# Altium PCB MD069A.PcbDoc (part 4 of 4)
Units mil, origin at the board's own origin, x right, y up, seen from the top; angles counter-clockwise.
Board outline 4569 x 3239 mil, 4 copper layers (Top Layer, Signal Layer 1, Signal Layer 2, Bottom Layer), stack 61.2 mil thick; 187 components, 103 nets, 560 pads, 220 vias.
Unrouted connection lines stored in the file: 7.
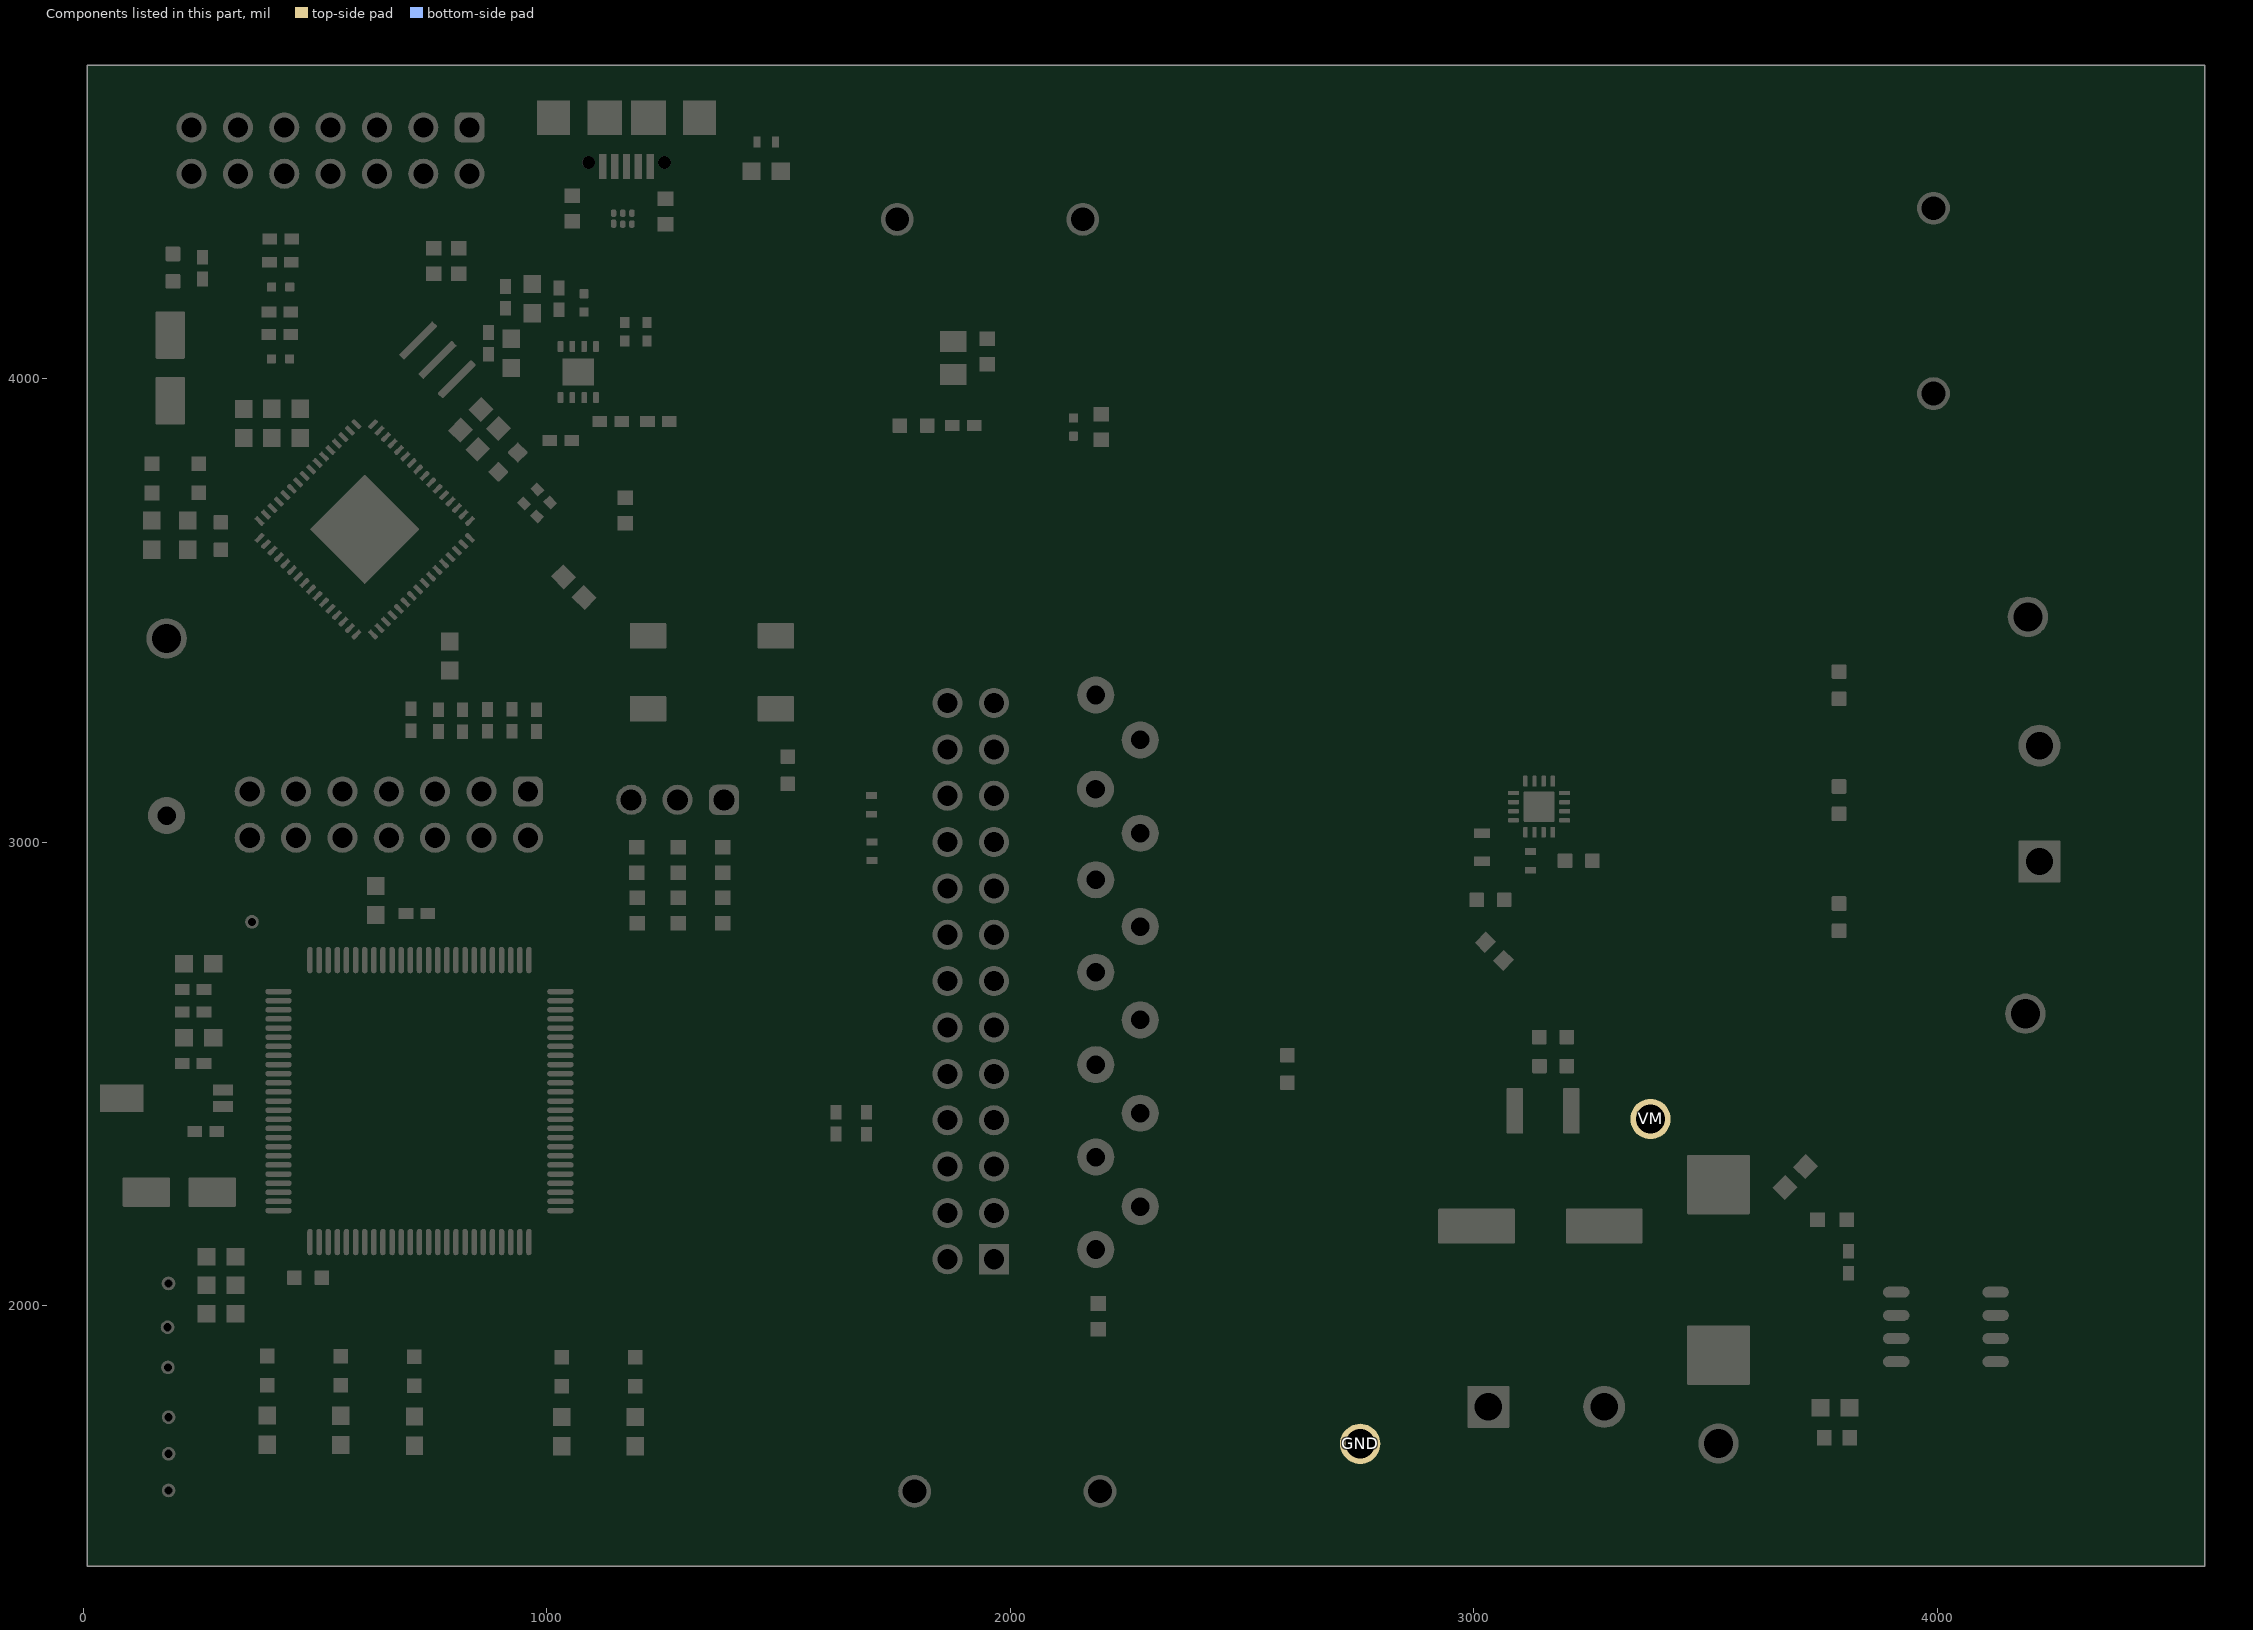
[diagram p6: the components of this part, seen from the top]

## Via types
v1: diameter 19.68, hole 13.78, Top Layer to Bottom Layer, tented both sides, 133 vias
v2: diameter 34, hole 16, Top Layer to Bottom Layer, tented both sides, 47 vias
v3: diameter 25/25/25/25 (per signal layer), hole 12, Top Layer to Bottom Layer, 19 vias
v4: diameter 19.68, hole 7.87, Top Layer to Bottom Layer, 16 vias
v5: diameter 19.68, hole 7.87, Top Layer to Bottom Layer, tented both sides, 5 vias

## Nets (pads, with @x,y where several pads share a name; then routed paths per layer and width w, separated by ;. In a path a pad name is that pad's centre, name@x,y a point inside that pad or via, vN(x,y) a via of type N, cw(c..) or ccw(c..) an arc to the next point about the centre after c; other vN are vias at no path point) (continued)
pads on no net: H2.0 H3.0 H4.0 H5.0 J9.6 J9.10 J9.12 J9.13 J9.14 J10.11 J10.12 J11.4 J11.MH1 J11.MH2 LBL1.0 P1.20 P1.22 SH-J1.0 SH-J2.0 SH-J3.0 SH-J4.0 SH-J5.0 SH-J6.0 SH-J7.0 SH-J8.0 SH-J9.0 SH-J10.0 SH-J11.0 SH-J12.0 SH-J19.0 SH-J29.0 SH-J31.0 SH-J32.0 SH-J33.0 SH-J34.0 SH-J36.0 U1.1 U1.2 U1.5 U1.6 U1.7 U1.8 U1.19 U1.24 U1.28 U1.30 U1.34 U1.35 U1.37 U1.38 U1.39 U1.40 U1.41 U1.46 U1.47 U1.48 U1.50 U1.52 U1.54 U1.55 U1.56 U1.57 U1.58 U1.59 U1.62 U1.67 U1.68 U1.69 U1.70 U1.71 U1.72 U1.73 U1.74 U1.75 U1.77 U1.78 U1.79 U1.80 U1.81 U1.82 U1.84 U1.85 U1.86 U1.92 U1.93 U1.94 U1.95 U1.99 U1.100 U2.3 U2.4 U2.5 U2.6 U2.7 U2.8 U2.10 U2.12 U2.13 U2.18 U2.19 U2.22 U2.23 U2.24 U2.25 U2.26 U2.27 U2.28 U2.29 U2.30 U2.31 U2.32 U2.33 U2.34 U2.35 U2.36 U2.41 U2.42 U2.45 U2.46 U2.47 U2.48 U3.2 U3.6 U3.7

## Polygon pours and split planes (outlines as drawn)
NetF1_1 on Signal Layer 2 "SIGNAL_LAYER_2_NETF1_1_P136" (solid, remove dead copper, pour order 136): 3186.98,1985.2 3177.14,1975.36 3177.14,1659.09 3704.72,1659.09 3704.72,1985.2
GND on Signal Layer 2 "SIGNAL_LAYER_2_GND_P275" (solid, pour order 275): 8,1438 4577,1438 4577,4677 8,4677
EZFET_VBUS on Signal Layer 2 "SIGNAL_LAYER_2_EZFET_VBUS_P199" (solid, remove dead copper, pour order 199): 881.67,4674.65 1506.38,4674.65 1506.38,4130.6 883.05,4130.6
GND on Bottom Layer "BOTTOM_LAYER_GND_P273" (solid, remove dead copper, pour order 273): 4577,4677 22.6,4677 22.6,1454.09 4577,1454.09
VM on Top Layer "Top Layer-VM" (solid, remove dead copper, pour order 284): 3182.2,1989.21 3596.49,1989.21 3733.74,1938.49 3733.74,2209.03 3289.22,2598.66 3289.21,2598.66 3214.52,2673.35 3214.52,3052.25 3182.23,3052.25 3182.23,2598.66 3182.2,2598.66
OUT2 on Top Layer "Top Layer-OUT2" (solid, remove dead copper, pour order 281): 3242.99,3101.78 4297.2,3101.78 4297.2,3333.76 4297.19,3534.66 4041.49,3534.66 4041.49,3333.76 3462.57,3333.76 3242.99,3114.18
OUT1 on Top Layer "Top Layer-OUT1" (solid, remove dead copper, pour order 276): 4041.71,2563.09 4297.47,2563.09 4297.47,3014.66 4297.07,3014.66 4297.07,3073.4 3242.86,3073.4 3242.86,3061.01 3462.44,2841.43 4041.71,2841.43
NetF1_1 on Top Layer "TOP_LAYER_NETF1_1_P201" (solid, remove dead copper, pour order 201): 3186.98,1985.2 3177.14,1975.36 3177.14,1659.09 3674.78,1659.09 3674.78,1985.2
GND on Top Layer "TOP_LAYER_GND_P283" (solid, remove dead copper, pour order 283): 5.69,1438.73 4574.69,1438.73 4574.69,4694.9 5.69,4694.9
GND on Signal Layer 1 "SIGNAL_LAYER_1_GND_P184" (solid, pour order 184): 15.78,4675 4577,4675 4577,1438 8,1438

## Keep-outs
Keep-Out Layer:
  text ".Layer_Name" at 577,-858.49 h25

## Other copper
Top Layer:
  region net EZFET_USB_Shield: 960,4649.2 960,4645.75 960,4426 1062.33,4426 1062.33,4485.1 1091.51,4508 1123.89,4508 1255.92,4508 1287.78,4476.14 1287.78,4431.31 1296.51,4431.31 1296.51,4432.8 1393.6,4432.8 1392,4648.75 1384.61,4648.75
  text ".Layer_Name" at 577,-858.49 h25
Bottom Layer:
  region net EZFET_USB_Shield: 1391,4428.4 1392,4427.4 1289,4427.4 1289,4500.38 1287.38,4502 1062.47,4502 1062.47,4429.47 1060,4427 1059.6,4427.4 952.18,4427.4 952.18,4502 951,4502 951,4649.88 951.31,4649 952.18,4649.88 1391,4649.88
  text ".Layer_Name" at 577,-858.49 h25

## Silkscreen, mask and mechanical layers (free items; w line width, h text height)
Top Overlay:
  lines w6: 755.3,3883.12 854.73,3783.69 959.5,3888.46 ; 755.3,3890.46 854.73,3989.89 ; 782.9,4491.95 782.9,4583.38 ; 783.57,4491.95 879.06,4491.78 ; 860.07,3989.89 959.5,3890.46 ; 910.63,3060.79 910.63,3152.21 ; 911.3,3060.79 1006.79,3060.61 ; 940.77,3869.73 1008.46,3802.04 1252.04,3802.04 ; 1225.34,3773.34 1298.75,3699.94 ; 1227.35,3773.34 1288.74,3834.74 ; 1289.41,3834.74 1362.15,3762 ; 1298.75,3697.94 1362.15,3761.33 ; 186.97,4397.12 879.06,4397.12 879.06,4586.43 186.97,4586.43 186.97,4397.12 ; 314.7,2965.96 1006.79,2965.96 1006.79,3155.27 314.7,3155.27 314.7,2965.96
  lines w10: 755.3,3883.12 755.3,3890.46 ; 854.73,3989.89 860.07,3989.89 ; 898.45,4506.4 898.45,4579.92 ; 959.5,3888.46 959.5,3890.46 ; 1022.26,3074.12 1022.26,3147.64 ; 1225.34,3773.34 1227.35,3773.34 ; 1288.74,3834.74 1289.41,3834.74 ; 1298.75,3697.94 1298.75,3699.94 ; 1362.15,3761.33 1362.15,3762 ; 2027.5,2701.11 2119.32,2701.11 ; 2027.5,3099.99 2114.65,3099.99 ; 2029.84,2501.67 2116.98,2501.67 ; 2029.84,2799.95 2208.81,2799.95 ; 2030.42,2099.28 2122.25,2099.28 ; 2031.01,2997.64 2205.88,2997.64 ; 2031.59,2202.8 2207.64,2202.8 ; 2031.59,2601.1 2211.15,2601.1 ; 2032.18,2901.13 2105.87,2901.13 ; 2032.76,2402.24 2214.66,2402.24 ; 2032.76,3301.19 2110.55,3301.19 ; 2033.35,2301.64 2114.64,2301.64 ; 2033.35,3203.51 2201.79,3203.51 ; 755.3,3890.46 755.3,3890.46 ; 940.77,3869.73 940.77,3869.73 ; 2944.68,2820.99 2945.02,2820.66 3294.35,2820.66 3296.35,2822.66 3296.35,3242.25 3294.02,3244.58 2944.68,3244.58 2944.68,2820.99
  text "For EZFET-LITE Flashing Only" at 198,4608 h25
  text "GND" at 3938.02,4439.94 h60
  text "GND" at 1886.66,4418.62 h60
  text "1" at 557,3922.8 h25
  text "'.PRJ_Number'.PCB_Rev" at 3036.12,3871.45 h60
  text "RST" at 1272.52,3536.47 h60
  text "OUT2" at 4402.98,3391.69 h60 r90
  text "3V3" at 2252,3308 h30
  text "GND" at 99.73,3290.74 h60
  text "DRV8214_34" at 2934.07,3286.54 h40
  text "GND" at 2352,3208.19 h30
  text "3V3" at 98.11,3140.29 h60
  text "A1" at 2292.71,3106.61 h30
  text "3" at 1143.68,3011.04 h25
  text "1" at 1423.77,3011.34 h25
  text "A0" at 2386.88,3001.92 h30
  text "nSLEEP" at 2296.22,2907.17 h30
  text "RC_OUT" at 92.54,2811.91 h40
  text "IN2" at 2389.8,2808.91 h30
  text "ID1" at 1198.65,2728.96 h25 r90
  text "ID2" at 1287.29,2728.96 h25 r90
  text "ID3" at 1391,2728.96 h25 r90
  text "IN1" at 2337.16,2700.13 h30
  text "SDA" at 2369,2611 h30
  text "OUT1" at 4397.64,2528.84 h60 r90
  text "SCL" at 2298.56,2503.61 h30
  text "VREF" at 2375.76,2405.35 h30
  text "IPROPI" at 2306.75,2307.09 h30
  text "RC_OUT" at 2385.71,2207.99 h30
  text "nFAULT" at 2287.45,2104.73 h30
  text "3V3" at 345.79,1685.48 h40 r90
  text "GND" at 1918.63,1663.93 h60
  text "MCU_STATUS" at 505.17,1627.46 h40 r90
  text "GUI_STATUS" at 667.13,1627.46 h40 r90
  text "STALL" at 986.32,1627.46 h40 r90
  text "nFAULT1" at 1145.83,1627.46 h40 r90
  text ".Layer_Name" at 577,-858.49 h25
Bottom Overlay:
  text ".Layer_Name" at 577,-858.49 h25
Top Paste:
  text ".Layer_Name" at 577,-858.49 h25
Bottom Paste:
  text ".Layer_Name" at 577,-858.49 h25
Top Solder:
  text ".Layer_Name" at 577,-858.49 h25
  text ".Layer_Name" at 577,-858.49 h25
Bottom Solder:
  text ".Layer_Name" at 577,-858.49 h25
Drill Guide:
  text ".Layer_Name" at 577,-858.49 h25
M1 Board Outline:
  circle w10: c4744.09,255.91 r70.87
  circle w10: c255.91,-255.91 r70.87
  lines w10: -1,1445 4,4647 ; -1,4681 4580,4678 ; 2,1434 4297,1438 ; 4577,4680 4578,1441
  text ".Layer_Name" at 577,-858.49 h25
M2 Board Dimensions:
  rectangle: 0,-275 125,-150
  rectangle: 125,-400 500,-275
  lines w7: 0,-275 1000,-275 ; 125,-400 125,-150 ; 250,-400 250,-150 ; 500,-400 500,-150 ; 750,-400 750,-150 ; 0,-400 1000,-400 1000,-150 0,-150 0,-400
  text ".Layer_Name" at 577,-858.49 h25
M3 3D STEP Top:
  text ".Layer_Name" at 577,-858.49 h25
M4 3D STEP Bottom:
  text ".Layer_Name" at 577,-858.49 h25
M5 Assembly Top:
  lines w10: -292,-930.17 6308,-930.17 ; -292,-726.83 6310,-726.83 ; -292,-523.5 -292,-1133.5 3713,-1133.5 6310,-1133.5 6310,-523.5 -291.5,-523.5 -291.5,-1133.5 1284,-1133.5 ; 2173,-1133.5 2173,-523.5 ; 3440,-726.83 3440,-523.5 ; 4280,-726.83 4280,-523.5 ; 4902,-1140 4902,-937.17
  text "COMPONENTS MARKED 'DNP' SHOULD NOT BE POPULATED." at 1153.5,-318.5 h25
  text "ASSEMBLY VARIANT:" at 1153,-434 h25
  text ".VariantName" at 2189,-434 h25
  text "PCB VIEWED FROM TOP SIDE" at -228.5,-655.67 h25
  text "BOARD #:" at 2248,-655.67 h25
  text ".PRJ_Number" at 2793.5,-655.67 h25
  text "REV:" at 3638,-655.67 h25
  text ".PCB_Rev" at 3929.5,-655.67 h25
  text "SVN REV:" at 4476,-655.67 h25
  text ".VersionControl_RevNumber" at 4982,-655.67 h25
  text "TID #:" at 2248,-859 h25
  text ".TID" at 2793.5,-859 h25
  text "PLOT NAME =" at -228.5,-1064.34 h25
  text ".plot_File_Name" at 577,-1064.34 h25
  text "GENERATED    :" at 2250,-1064.34 h25
  text ".Print_Date" at 3119.5,-1064.34 h25
  text ".Print_Time" at 3848.5,-1064.34 h25
  text "TEXAS INSTRUMENTS" at 5113,-1064.34 h25
M6 Assembly Bottom:
  lines w10: -292.5,-727.33 6309.5,-727.33 ; -290.5,-930.67 6309.5,-930.67 ; 1115.5,-1140.5 1115.5,-937.67 ; 1737.5,-727.33 1737.5,-524 ; 2577.5,-727.33 2577.5,-524 ; 3844.5,-1134 3844.5,-524 ; 4733.5,-1134 6309,-1134 6309,-524 -292.5,-524 -292.5,-1134 2304.5,-1134 6309.5,-1134 6309.5,-524
  text "COMPONENTS MARKED 'DNP' SHOULD NOT BE POPULATED." at 6102,-318 h25
  text ".VariantName" at 5058,-434 h25
  text "ASSEMBLY VARIANT:" at 6097,-434 h25
  text ".VersionControl_RevNumber" at 1035.5,-656.17 h25
  text "SVN REV:" at 1541.5,-656.17 h25
  text ".PCB_Rev" at 2088,-656.17 h25
  text "REV:" at 2379.5,-656.17 h25
  text ".PRJ_Number" at 3224,-656.17 h25
  text "BOARD #:" at 3769.5,-656.17 h25
  text "PCB VIEWED FROM BOTTOM SIDE" at 6246,-656.17 h25
  text ".TID" at 3224,-859.5 h25
  text "TID #:" at 3769.5,-859.5 h25
  text "TEXAS INSTRUMENTS" at 904.5,-1064.84 h25
  text ".Print_Time" at 2169,-1064.84 h25
  text ".Print_Date" at 2898,-1064.84 h25
  text "GENERATED    :" at 3767.5,-1064.84 h25
  text ".plot_File_Name" at 5440.5,-1064.84 h25
  text "PLOT NAME =" at 6246,-1064.84 h25
M9 Title Sheet:
  drawing of 57 lines, arcs and shapes, not listed
  text "1" at 739.84,8036.5 h25
  text "2" at 3235.5,8036.5 h25
  text "3" at 5724.84,8036.5 h25
  text "4" at 8231.51,8036.5 h25
  text "5" at 10730.5,8036.5 h25
  text "6" at 13235.5,8036.5 h25
  text "A" at -416.5,6893.5 h25
  text "A" at 14383.5,6893.5 h25
  text "B" at -416.5,4513.5 h25
  text "B" at 14383.5,4513.5 h25
  text "C" at -416.5,2138.5 h25
  text "C" at 14383.5,2138.5 h25
  text "PROJECT TITLE:" at 11343.5,277.5 h25
  text ".PRJ_Title" at 11393.5,144.17 h25
  text "DESIGNED FOR:" at 11343.5,-23.5 h25
  text ".PRJ_Customer" at 11393.5,-163.5 h25
  text "D" at -416.5,-231.5 h25
  text "D" at 14383.5,-231.5 h25
  text "FILE NAME:" at 11343.5,-323.5 h25
  text ".PCB_File_Name_No_Path" at 11393.5,-443.5 h25
  text "Texas Instruments (TI) and/or its licensors do not warrant the accuracy or completeness of this specification" at 6374,-605.34 h25
  text "ENGINEER:" at 11343.5,-613.5 h25
  text "LAYOUT BY:" at 12848.5,-613.5 h25
  text "or any information contained therein. TI and/or its licensors do not warrant that this design will meet" at 6329.01,-718 h25
  text ".PRJ_Engineer" at 11393.5,-768.49 h25
  text ".PCB_Layout" at 12899,-768.49 h25
  text "the specifications, will be suitable for your application or fit for any particular purpose, or will operate in" at 6329.01,-830.67 h25
  text ".Layer_Name" at 577,-858.49 h25
  text "ALTIUM DESIGNER VERSION:" at 12848.5,-923.5 h25
  text "an implementation. TI and/or its licensors do not warrant that the design is production worthy. You should" at 6329.01,-943.33 h25
  text "completely validate and test your design implementation to confirm the system functionality for your application." at 6374,-1056 h25
  text ".print_Scale" at 11393.5,-1056.83 h25
  text ".Application_BuildNumber" at 12899,-1056.83 h25
  text "1" at 739.84,-1263.5 h25
  text "2" at 3235.5,-1263.5 h25
  text "3" at 5724.84,-1263.5 h25
  text "4" at 8231.51,-1263.5 h25
  text "5" at 10730.5,-1263.5 h25
  text "6" at 13235.5,-1263.5 h25
M10 Fab Notes:
  drawing of 189 lines, arcs and shapes, not listed
  text "DESIGN INFORMATION" at 12382.02,6356.17 h25
  text "MIN. TRACK WIDTH:" at 11737.46,6224.05 h25
  text "8" at 12833.7,6224.05 h25
  text "MIL" at 12988.46,6224.05 h25
  text "MIN. CLEARANCE:" at 11737.46,6099.92 h25
  text "0.2" at 12773.7,6099.93 h25
  text "mm" at 12988.46,6099.92 h25
  text "MIN. VIA PAD SIZE:" at 11737.46,5975.8 h25
  text "24" at 12803.71,5975.8 h25
  text "MIL" at 12988.46,5975.8 h25
  text "0.05mm (2MIL)" at 12432.46,5845.9 h25
  text "MINIMUM ANNULAR RING" at 11408.23,5837.67 h25
  text "EXTERNAL" at 13140.46,5837.67 h25
  text "PER" at 11608.23,5727.55 h25
  text "IPC-D-275 CLASS 2 LEVEL C" at 11828.23,5727.54 h25
  text "MIL, HOLES" at 13316.46,5627.07 h25
  text "+/-" at 12924,5618.48 h25
  text "+/-" at 13778,5618.48 h25
  text "REGISTRATION TOLERANCES:" at 11408.23,5617.42 h25
  text "METAL" at 12608,5617.42 h25
  text "5" at 13184.2,5617.42 h25
  text "3" at 14017.2,5617.42 h25
  text "MIL" at 14133.46,5617.42 h25
  text "HOLE SIZE TOLERANCE (UNLESS OTHERWISE SPECIFIED):" at 11408.23,5519.1 h25
  text "+/-" at 13778,5516.23 h25
  text "3" at 14017.2,5515.17 h25
  text "MIL" at 14133.46,5515.17 h25
  text "MATERIAL:" at 11333.46,5377.52 h25
  text "FR-4 High Tg" at 12319.9,5249 h25
  text "X" at 12175.46,5241.01 h25
  text "FR-408" at 11754.46,5236.49 h25
  text "OTHER" at 13242.46,5236.49 h25
  text "62 MIL (1.6mm) +/-10%" at 12074.56,5093.46 h25
  text "X" at 11954.46,5091.01 h25
  text "THICKNESS:" at 11408.23,5085.24 h25
  text "OTHER" at 13359.46,5085.24 h25
  text "TOLERANCE:" at 11408.23,4946.92 h25
  text "X" at 12256.46,4946.92 h25
  text "ANSI IPC-6012 TYPE 3 CLASS 2" at 12434.48,4946.92 h25
  text "OTHER +/-" at 12434.46,4802.73 h25
  text "BOW & TWIST:" at 11408.23,4657.54 h25
  text "X" at 12256.46,4657.54 h25
  text "ANSI IPC-6012 TYPE 3 CLASS 2" at 12434.48,4657.54 h25
  text "OTHER +/-" at 12434.46,4510.85 h25
  text "DRILLING:" at 11333.46,4380.23 h25
  text "NC_DRILL FILES" at 13094.46,4275.04 h25
  text "REFERENCE:" at 11408.23,4271.1 h25
  text "X" at 12065.46,4271.01 h25
  text "AS SHOWN" at 12243.46,4271.1 h25
  text "X" at 12966.46,4271.1 h25
  text "OTHER" at 13392.46,4128.85 h25
  text "PTH COPPER THICKNESS:" at 11407.91,4125.32 h25
  text "X" at 12547.14,4125.32 h25
  text "20-30 um" at 12675.14,4125.32 h25
  text "BOARD FINISH:" at 11333.46,3977.73 h25
  text "SILKSCREEN:" at 11488.68,3867.6 h25
  text "X" at 12446.46,3867.6 h25
  text "TOP" at 12563.46,3867.6 h25
  text "X" at 12956.46,3867.6 h25
  text "BOTTOM" at 13074.46,3867.6 h25
  text "SILKSCREEN COLOR:" at 11488.68,3712.41 h25
  text "X" at 12445.46,3712.41 h25
  text "WHITE" at 12563.46,3712.41 h25
  text "OTHER" at 13074.46,3712.41 h25
  text "X" at 12576.46,3568.96 h25
  text "GREEN" at 12694.46,3568.96 h25
  text "OTHER" at 13312.46,3568.96 h25
  text "SOLDER RESIST COLOR:" at 11488.68,3562.1 h25
  text "X" at 12576.46,3414.71 h25
  text "MATTE" at 12694.46,3414.71 h25
  text "SEMI-GLOSS" at 13312,3414.07 h25
  text "IMMERSION GOLD (ENIG)" at 12394.46,3241.94 h25
  text "ENEPIG" at 13732,3234.72 h25
  text "SURFACE FINISH:" at 11333.46,3233.72 h25
  text "X" at 12216.46,3233.72 h25
  text "IMM. TIN/SILVER OR EQUIV" at 11663,3096.4 h25
  text "OTHER" at 13094.46,3092.47 h25
  text "ARRAY/PANEL:" at 11333.46,2937.09 h25
  text "CUT AND TRIM PER M1 BOARD OUTLINE" at 12394.46,2928.87 h25
  text "N.C. ROUTE" at 12394.46,2792.9 h25
  text "X" at 13082.46,2792.9 h25
  text "V. SCORE" at 13260.46,2792.9 h25
  text "CERTIFICATION:" at 11333.46,2663.77 h25
  text "MATERIALS AND WORKMANSHIP FOR ALL PCBS" at 12058.46,2663.77 h25
  text "TO MEET OR EXCEED THE REQUIREMENTS OF:" at 12058.46,2569.71 h25
  text "X" at 11695.97,2441.08 h25
  text "ANSI IPC-A-600F CLASS ->" at 11823.96,2441.08 h25
  text "X" at 13471.97,2441.08 h25
  text "2" at 13581.96,2441.08 h25
  text "1" at 13266.96,2439.58 h25
  text "3" at 13935.96,2439.58 h25
  text "X" at 12507.97,2293.39 h25
  text "RoHS" at 12635.96,2293.39 h25
  text "OTHER" at 13280.36,2293.39 h25
  text "PER ORDER" at 13677.42,2293.39 h25
  text "ALL BOARDS MUST MEET OR EXCEED UL94-V0 REQUIREMENTS." at 11361,2139.57 h25
  text "PCB MUST BEAR THE UL94V-0 UL REGISTERED MATERIAL ID NUMBER" at 11361,2023.5 h25
  text "ADDITIONAL REQUIREMENTS:" at 11333.46,1854.08 h25
  text "MICROSECTION:" at 11408.23,1746.95 h25
  text "YES" at 12313.96,1746.95 h25
  text "REQUIRED" at 13175.46,1602.62 h25
  text "BARE BOARD ELEC. TEST:" at 11408.23,1599.76 h25
  text "NONE" at 12713.96,1599.76 h25
  text "X" at 13057.46,1599.76 h25
  text "PER ORDER" at 13767.46,1599.76 h25
  text "XX MIL VIAS REQUIRE NON-CONDUCTIVE FILL AND PLANARIZE" at 11576.38,1394.82 h25
  text "XX MIL VIAS REQUIRE CONDUCTIVE FILL AND PLANARIZE" at 11584.38,1290.84 h25
  text "OUTER XX MIL TRACES REQUIRE 50 OHM SINGLE-ENDED IMPEDANCE" at 11583.39,1127.46 h25
  text "LAYER 2 & 3 (INNER LAYERS) XX MIL WIDE, XX MIL SPACE / TRACES REQUIRE 100 OHM DIFFERENTIAL IMPEDANCE" at 11575.39,891.74 h25
  text ".Layer_Name" at 577,-858.49 h25
M11 Gerber Information:
  lines w10: -292,-930.17 6308,-930.17 ; -292,-726.83 6310,-726.83 ; -292,-523.5 -292,-1133.5 3713,-1133.5 6310,-1133.5 6310,-523.5 -291.5,-523.5 -291.5,-1133.5 1284,-1133.5 ; 2173,-1133.5 2173,-523.5 ; 3440,-726.83 3440,-523.5 ; 4280,-726.83 4280,-523.5 ; 4902,-1140 4902,-937.17
  text "ALL ARTWORK VIEWED FROM TOP SIDE" at -228.5,-655.67 h25
  text "BOARD #:" at 2248,-655.67 h25
  text ".PRJ_Number" at 2793.5,-655.67 h25
  text "REV:" at 3638,-655.67 h25
  text ".PCB_Rev" at 3929.5,-655.67 h25
  text "SVN REV:" at 4476,-655.67 h25
  text ".VersionControl_RevNumber" at 4982,-655.67 h25
  text "LAYER NAME =" at -228.5,-858.49 h25
  text "TID #:" at 2248,-859 h25
  text ".TID" at 2793.5,-859 h25
  text "PLOT NAME =" at -228.5,-1064.34 h25
  text ".plot_File_Name" at 577,-1064.34 h25
  text "GENERATED    :" at 2250,-1064.34 h25
  text ".Print_Date" at 3119.5,-1064.34 h25
  text ".Print_Time" at 3848.5,-1064.34 h25
  text "TEXAS INSTRUMENTS" at 5113,-1064.34 h25
M12 Stackup:
  drawing of 306 lines, arcs and shapes, not listed
  text "Layer" at 9741.35,7906.5 h25
  text "Name" at 9923.81,7906.5 h25
  text "Material" at 10327.03,7906.5 h25
  text "Thickness" at 10696.94,7906.5 h25
  text "Constant" at 10979.37,7906.5 h25
  text "Board Layer Stack" at 11228.48,7906.5 h25
  text "Top Overlay" at 9923.81,7856.5 h25
  text "Top Solder" at 9923.81,7806.5 h25
  text "Solder Resist" at 10327.03,7806.5 h25
  text "0.40mil" at 10696.94,7806.5 h25
  text "3.5" at 10979.37,7806.5 h25
  text "1" at 9741.35,7756.5 h25
  text "Top Layer" at 9923.81,7756.5 h25
  text "2.80mil" at 10696.94,7756.5 h25
  text "Dielectric 1" at 9923.81,7706.5 h25
  text "FR4 370" at 10327.03,7706.5 h25
  text "11.40mil" at 10696.94,7706.5 h25
  text "4.2" at 10979.37,7706.5 h25
  text "2" at 9741.35,7656.5 h25
  text "Signal Layer 1" at 9923.81,7656.5 h25
  text "1.40mil" at 10696.94,7656.5 h25
  text "Dielectric 2" at 9923.81,7606.5 h25
  text "FR4 370" at 10327.03,7606.5 h25
  text "30.00mil" at 10696.94,7606.5 h25
  text "4.2" at 10979.37,7606.5 h25
  text "3" at 9741.35,7556.5 h25
  text "Signal Layer 2" at 9923.81,7556.5 h25
  text "1.40mil" at 10696.94,7556.5 h25
  text "Dielectric 3" at 9923.81,7506.5 h25
  text "FR4 370" at 10327.03,7506.5 h25
  text "11.40mil" at 10696.94,7506.5 h25
  text "4.2" at 10979.37,7506.5 h25
  text "4" at 9741.35,7456.5 h25
  text "Bottom Layer" at 9923.81,7456.5 h25
  text "2.80mil" at 10696.94,7456.5 h25
  text "Bottom Solder" at 9923.81,7406.5 h25
  text "Solder Resist" at 10327.03,7406.5 h25
  text "0.40mil" at 10696.94,7406.5 h25
  text "3.5" at 10979.37,7406.5 h25
  text "Bottom Overlay" at 9923.81,7356.5 h25
  text ".Layer_Name" at 577,-858.49 h25
M13 Component Bodies Top:
  text ".Layer_Name" at 577,-858.49 h25
M14 Component Bodies Bottom:
  text ".Layer_Name" at 577,-858.49 h25
M15 Courtyards Top:
  text ".Layer_Name" at 577,-858.49 h25
M16 Courtyards Bottom:
  text ".Layer_Name" at 577,-858.49 h25
Drill Drawing:
  circle w10: c76.03,7831.35 r6.9
  circle w10: c76.03,7831.35 r11.5
  circle w10: c76.03,7365.65 r11.5
  lines w10: 64.53,7256.41 70.28,7256.41 76.03,7250.66 81.78,7256.41 87.53,7256.41 81.78,7262.16 87.53,7267.91 81.78,7267.91 76.03,7273.66 70.28,7267.91 64.53,7267.91 70.28,7262.16 64.53,7256.41 ; 64.53,7302.41 76.03,7308.16 87.53,7302.41 81.78,7313.91 87.53,7325.4 76.03,7319.65 64.53,7325.4 70.28,7313.91 64.53,7302.41 ; 64.53,7428.89 87.53,7428.89 76.03,7405.89 64.53,7428.89 ; 64.53,7480.64 87.53,7480.64 76.03,7457.64 64.53,7480.64 ; 64.53,7515.13 70.28,7515.13 70.28,7509.38 81.78,7509.38 81.78,7515.13 87.53,7515.13 87.53,7526.63 81.78,7526.63 81.78,7532.38 70.28,7532.38 70.28,7526.63 64.53,7526.63 64.53,7515.13 ; 64.53,7572.63 76.03,7561.13 87.53,7572.63 76.03,7584.12 64.53,7572.63 ; 64.53,7612.87 76.03,7618.62 87.53,7612.87 81.78,7624.37 87.53,7635.87 76.03,7630.12 64.53,7635.87 70.28,7624.37 64.53,7612.87 ; 64.53,7664.61 64.53,7670.36 70.28,7676.11 64.53,7681.86 64.53,7687.61 70.28,7687.61 76.03,7681.86 81.78,7687.61 87.53,7687.61 87.53,7681.86 81.78,7676.11 87.53,7670.36 87.53,7664.61 81.78,7664.61 76.03,7670.36 70.28,7664.61 64.53,7664.61 ; 64.53,7716.36 87.53,7716.36 87.53,7739.36 64.53,7739.36 64.53,7716.36 ; 64.53,7768.1 87.53,7768.1 87.53,7791.1 64.53,7791.1 64.53,7768.1 ; 64.53,7877.34 70.28,7877.34 70.28,7871.59 81.78,7871.59 81.78,7877.34 87.53,7877.34 87.53,7888.84 81.78,7888.84 81.78,7894.59 70.28,7894.59 70.28,7888.84 64.53,7888.84 64.53,7877.34 ; 69.13,7307.01 76.03,7310.46 82.93,7307.01 79.48,7313.91 82.93,7320.8 76.03,7317.35 69.13,7320.8 72.58,7313.91 69.13,7307.01 ; 69.13,7476.04 82.93,7476.04 76.03,7462.24 69.13,7476.04 ; 69.13,7772.7 82.93,7772.7 82.93,7786.5 69.13,7786.5 69.13,7772.7 ; 69.13,7879.64 72.58,7879.64 72.58,7876.19 79.48,7876.19 79.48,7879.64 82.93,7879.64 82.93,7886.54 79.48,7886.54 79.48,7889.99 72.58,7889.99 72.58,7886.54 69.13,7886.54 69.13,7879.64
  lines w12: 41.86,7235.14 1386.26,7235.14 ; 41.86,7907.81 1386.26,7907.81 ; 182.41,7183.4 182.41,7959.56 ; 320.52,7183.4 320.52,7959.56 ; 585.3,7183.4 585.3,7959.56 ; 693.1,7183.4 693.1,7959.56 ; 849.16,7183.4 849.16,7959.56 ; 1150.64,7183.4 1150.64,7959.56 ; 41.86,7183.4 1386.26,7183.4 1386.26,7959.56 41.86,7959.56 41.86,7183.4
  text "Symbol" at 72.9,7923.33 h30
  text "Quantity" at 197.94,7923.33 h30
  text "Finished Hole Size" at 336.04,7923.33 h30
  text "Plated" at 600.82,7923.33 h30
  text "Hole Type" at 708.63,7923.33 h30
  text "Drill Layer Pair" at 864.68,7923.33 h30
  text "Hole Tolerance" at 1166.16,7923.33 h30
  text "2" at 197.94,7871.59 h25
  text "27.56mil (0.700mm)" at 336.04,7871.59 h25
  text "NPTH" at 600.82,7871.59 h25
  text "Round" at 708.63,7871.59 h25
  text "Top Layer - Bottom Layer" at 864.68,7871.59 h25
  text "21" at 197.94,7819.85 h25
  text "7.87mil (0.200mm)" at 336.04,7819.85 h25
  text "PTH" at 600.82,7819.85 h25
  text "Round" at 708.63,7819.85 h25
  text "Top Layer - Bottom Layer" at 864.68,7819.85 h25
  text "19" at 197.94,7768.1 h25
  text "12.00mil (0.305mm)" at 336.04,7768.1 h25
  text "PTH" at 600.82,7768.1 h25
  text "Round" at 708.63,7768.1 h25
  text "Top Layer - Bottom Layer" at 864.68,7768.1 h25
  text "133" at 197.94,7716.36 h25
  text "13.78mil (0.350mm)" at 336.04,7716.36 h25
  text "PTH" at 600.82,7716.36 h25
  text "Round" at 708.63,7716.36 h25
  text "Top Layer - Bottom Layer" at 864.68,7716.36 h25
  text "47" at 197.94,7664.61 h25
  text "16.00mil (0.406mm)" at 336.04,7664.61 h25
  text "PTH" at 600.82,7664.61 h25
  text "Round" at 708.63,7664.61 h25
  text "Top Layer - Bottom Layer" at 864.68,7664.61 h25
  text "7" at 197.94,7612.87 h25
  text "17.72mil (0.450mm)" at 336.04,7612.87 h25
  text "PTH" at 600.82,7612.87 h25
  text "Round" at 708.63,7612.87 h25
  text "Top Layer - Bottom Layer" at 864.68,7612.87 h25
  text "14" at 197.94,7561.13 h25
  text "40.00mil (1.016mm)" at 336.04,7561.13 h25
  text "PTH" at 600.82,7561.13 h25
  text "Round" at 708.63,7561.13 h25
  text "Top Layer - Bottom Layer" at 864.68,7561.13 h25
  text "26" at 197.94,7509.38 h25
  text "43.31mil (1.100mm)" at 336.04,7509.38 h25
  text "PTH" at 600.82,7509.38 h25
  text "Round" at 708.63,7509.38 h25
  text "Top Layer - Bottom Layer" at 864.68,7509.38 h25
  text "28" at 197.94,7457.64 h25
  text "43.31mil (1.100mm)" at 336.04,7457.64 h25
  text "PTH" at 600.82,7457.64 h25
  text "Round" at 708.63,7457.64 h25
  text "Top Layer - Bottom Layer" at 864.68,7457.64 h25
  text "+/-1.97mil" at 1166.16,7457.64 h25
  text "3" at 197.94,7405.89 h25
  text "45.28mil (1.150mm)" at 336.04,7405.89 h25
  text "PTH" at 600.82,7405.89 h25
  text "Round" at 708.63,7405.89 h25
  text "Top Layer - Bottom Layer" at 864.68,7405.89 h25
  text "6" at 197.94,7354.15 h25
  text "51.18mil (1.300mm)" at 336.04,7354.15 h25
  text "PTH" at 600.82,7354.15 h25
  text "Round" at 708.63,7354.15 h25
  text "Top Layer - Bottom Layer" at 864.68,7354.15 h25
  text "4" at 197.94,7302.41 h25
  text "59.06mil (1.500mm)" at 336.04,7302.41 h25
  text "PTH" at 600.82,7302.41 h25
  text "Round" at 708.63,7302.41 h25
  text "Top Layer - Bottom Layer" at 864.68,7302.41 h25
  text "6" at 197.94,7250.66 h25
  text "63.00mil (1.600mm)" at 336.04,7250.66 h25
  text "PTH" at 600.82,7250.66 h25
  text "Round" at 708.63,7250.66 h25
  text "Top Layer - Bottom Layer" at 864.68,7250.66 h25
  text "316 Total" at 197.94,7198.92 h25
  text ".Layer_Name" at 577,-858.49 h25
Mechanical 17:
  text ".Layer_Name" at 577,-858.49 h25
Mechanical 18:
  text ".Layer_Name" at 577,-858.49 h25
Mechanical 19:
  text ".Layer_Name" at 577,-858.49 h25

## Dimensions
32,1742.75 to 4577,1438 on M1 Board Outline
2,1434 to 4577,1438 on M2 Board Dimensions
8,1438 to 4579,4687 on M2 Board Dimensions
